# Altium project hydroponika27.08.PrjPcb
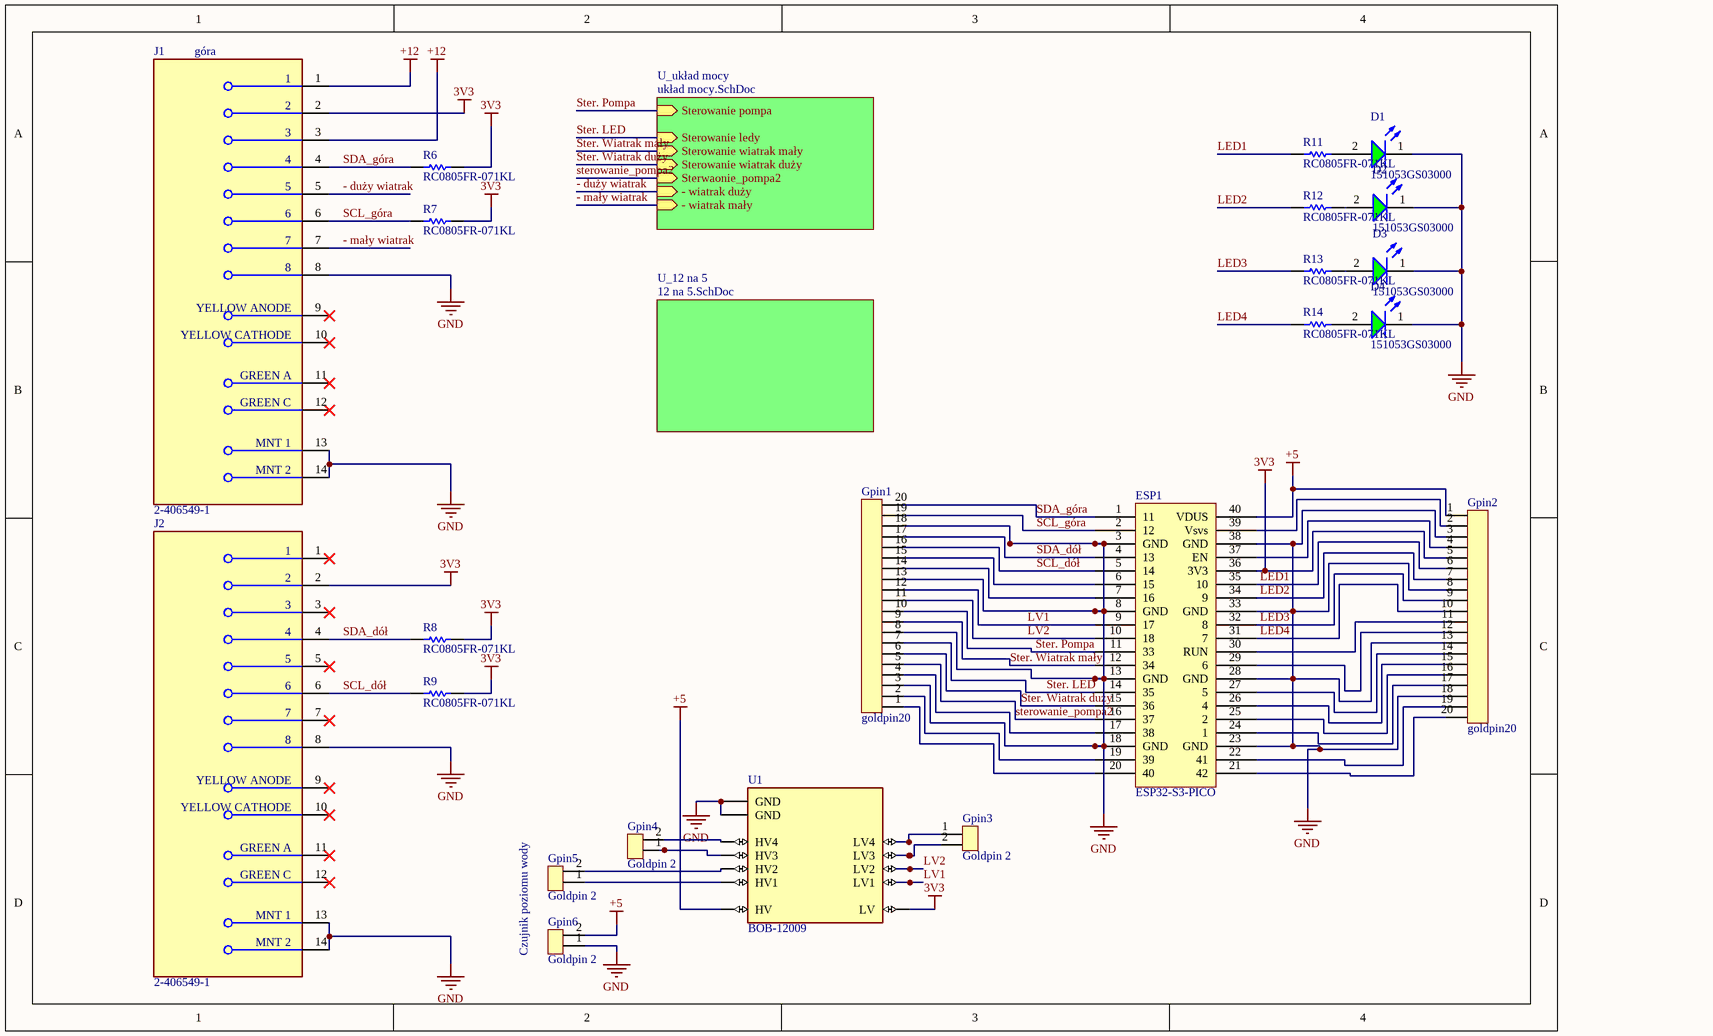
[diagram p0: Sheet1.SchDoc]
2 sheets, 30 parts. Net scope: hierarchical (ports join the sheet entries above them; power ports are global).
Board file: PCB1.PcbDoc
Sheets:
  Sheet1.SchDoc
    U_12 na 5 = 12 na 5.SchDoc

## Sheet Sheet1.SchDoc
size A4; SheetNumber: 1; SheetTotal: 3

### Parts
D1  151053GS03000  [WL-TMRW_D5.8H11.7]
D2  151053GS03000  [WL-TMRW_D5.8H11.7]
D3  151053GS03000  [WL-TMRW_D5.8H11.7]
D4  151053GS03000  [WL-TMRW_D5.8H11.7]
ESP1  ESP32-S3-PICO  [DIP40_ESP32]
Gpin1  goldpin20  [PCBComponent_1]
Gpin2  goldpin20  [PCBComponent_1]
Gpin3  Goldpin 2  [Goldpin 2]
Gpin4  Goldpin 2  [Goldpin 2]
Gpin5  Goldpin 2  [Goldpin 2]
Gpin6  Goldpin 2  [Goldpin 2]
J1  2-406549-1  [FP-2-406549-1-MFG]
J2  2-406549-1  [FP-2-406549-1-MFG]
R6  RC0805FR-071KL  [RESC2013X60X35ML10T20]
R7  RC0805FR-071KL  [RESC2013X60X35ML10T20]
R8  RC0805FR-071KL  [RESC2013X60X35ML10T20]
R9  RC0805FR-071KL  [RESC2013X60X35ML10T20]
R11  RC0805FR-071KL  [RESC2013X60X35ML10T20]
R12  RC0805FR-071KL  [RESC2013X60X35ML10T20]
R13  RC0805FR-071KL  [RESC2013X60X35ML10T20]
R14  RC0805FR-071KL  [RESC2013X60X35ML10T20]
U1  BOB-12009  [CONV_BOB-12009]

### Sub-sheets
U_12 na 5 = 12 na 5.SchDoc: no entries
U_układ mocy = układ mocy.SchDoc (file not in this document): Sterowanie pompa (in), Sterowanie ledy (in), Sterowanie wiatrak mały (in), Sterowanie wiatrak duży (in), - wiatrak duży (in), - wiatrak mały (in), Sterwaonie_pompa2 (in)

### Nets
3V3: ESP1.36(3V3) Gpin2.5 J1.2 J2.2 R6.2 R7.2 R8.2 R9.2 U1.LV
+5: ESP1.40(VDUS) Gpin2.1 Gpin6.2 U1.HV  [project net +vout_5]
+12: J1.1 J1.3  [project net +vin_12]
GND: D1.1(K) D2.1(K) D3.1(K) D4.1(K) ESP1.3(GND) ESP1.8(GND) ESP1.13(GND) ESP1.18(GND) ESP1.23(GND) ESP1.28(GND) ESP1.33(GND) ESP1.38(GND) Gpin1.3 Gpin1.8 Gpin1.13 Gpin1.18 Gpin2.3 Gpin2.8 Gpin2.13 Gpin2.18 Gpin6.1 J1.8 J1.13(MNT_1) J1.14(MNT_2) J2.8 J2.13(MNT_1) J2.14(MNT_2) U1.GND_1(GND) U1.GND_2(GND)  [project net - vout_5]
- duży wiatrak: J1.5 ; sheet U_układ mocy/- wiatrak duży
- mały wiatrak: J1.7 ; sheet U_układ mocy/- wiatrak mały
LED1: ESP1.35(10) Gpin2.6 R11.1
LED2: ESP1.34(9) Gpin2.7 R12.1
LED3: ESP1.32(8) Gpin2.9 R13.1
LED4: ESP1.31(7) Gpin2.10 R14.1
LV1: ESP1.9(17) Gpin1.12 U1.LV1
LV2: ESP1.10(18) Gpin1.11 U1.LV2
SCL_dół: ESP1.5(14) Gpin1.16 J2.6 R9.1
SCL_góra: ESP1.2(12) Gpin1.19 J1.6 R7.1
SDA_dół: ESP1.4(13) Gpin1.17 J2.4 R8.1
SDA_góra: ESP1.1(11) Gpin1.20 J1.4 R6.1
Ster. LED: ESP1.14(35) Gpin1.7 ; sheet U_układ mocy/Sterowanie ledy
Ster. Pompa: ESP1.11(33) Gpin1.10 ; sheet U_układ mocy/Sterowanie pompa
Ster. Wiatrak duży: ESP1.15(36) Gpin1.6 ; sheet U_układ mocy/Sterowanie wiatrak duży
Ster. Wiatrak mały: ESP1.12(34) Gpin1.9 ; sheet U_układ mocy/Sterowanie wiatrak mały
sterowanie_pompa2: ESP1.16(37) Gpin1.5 ; sheet U_układ mocy/Sterwaonie_pompa2
NetD1_2: D1.2(A) R11.2
NetD2_2: D2.2(A) R12.2
NetD3_2: D3.2(A) R13.2
NetD4_2: D4.2(A) R14.2
NetESP1_6: ESP1.6(15) Gpin1.15
NetESP1_7: ESP1.7(16) Gpin1.14
NetESP1_17: ESP1.17(38) Gpin1.4
NetESP1_19: ESP1.19(39) Gpin1.2
NetESP1_20: ESP1.20(40) Gpin1.1
NetESP1_21: ESP1.21(42) Gpin2.20
NetESP1_22: ESP1.22(41) Gpin2.19
NetESP1_24: ESP1.24(1) Gpin2.17
NetESP1_25: ESP1.25(2) Gpin2.16
NetESP1_26: ESP1.26(4) Gpin2.15
NetESP1_27: ESP1.27(5) Gpin2.14
NetESP1_29: ESP1.29(6) Gpin2.12
NetESP1_30: ESP1.30(RUN) Gpin2.11
NetESP1_37: ESP1.37(EN) Gpin2.4
NetESP1_39: ESP1.39(Vsvs) Gpin2.2
NetGpin3_1: Gpin3.1 U1.LV4
NetGpin3_2: Gpin3.2 U1.LV3
NetGpin4_1: Gpin4.1 U1.HV3
NetGpin4_2: Gpin4.2 U1.HV4
NetGpin5_1: Gpin5.1 U1.HV1
NetGpin5_2: Gpin5.2 U1.HV2

Not connected (* = marked no-connect by the designer): J1 9(YELLOW_ANODE)* 10(YELLOW_CATHODE)* 11(GREEN_A)* 12(GREEN_C)*; J2 1* 3* 5* 7* 9(YELLOW_ANODE)* 10(YELLOW_CATHODE)* 11(GREEN_A)* 12(GREEN_C)*

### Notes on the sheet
- góra
- Czujnik poziomu wody

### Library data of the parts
D1-D4 = CMP-1489-00005-2: NexarPartId: 29717817; Viewing Angle: 30°; Color: Green; Wavelength: 522nm; Max Reverse Voltage (DC): 5V; Test Current: 20mA; Forward Current: 100mA; Forward Voltage: 3.4V; Lens Style: Circular, Clear, Round; Luminous Intensity: 10cd; Lens Size: 5mm; Peak Wavelength: 515nm
J1 J2 = CMP-2000-05541-2: CONN MOD JACK 8P8C R/A SHIELDED; Max Voltage Rating (AC): 150V; Number of Contacts: 8; PCB Mounting Orientation: Right Angle; Direction: Up; Pitch: 2.03mm; Number of Ports: 1; Gender: Female; Tail Length: 2.54mm; Current Rating: 1.5A; Keyed: No; Approvals: UL; PCB Thickness: 1.57mm; Element Configuration: Single
R6-R9 R11-R14 = CMP-2100-03671-1: Chip Resistor, 1 KOhm, +/- 1%, 125 mW, -55 to 155 degC, 0805 (2012 Metric), RoHS, Tape and Reel; Manufacturer: Yageo; Temperature Coefficient: 100ppm/degreesC; Voltage Rating (DC): 150V; Max Power Dissipation: 125mW; Resistance: 1KOhm
U1 = BOB-12009: BSS138 - Logic-Level Translator Interface Evaluation Board; MF: SparkFun

## Sheet 12 na 5.SchDoc
size A4; SheetNumber: 3; SheetTotal: 3
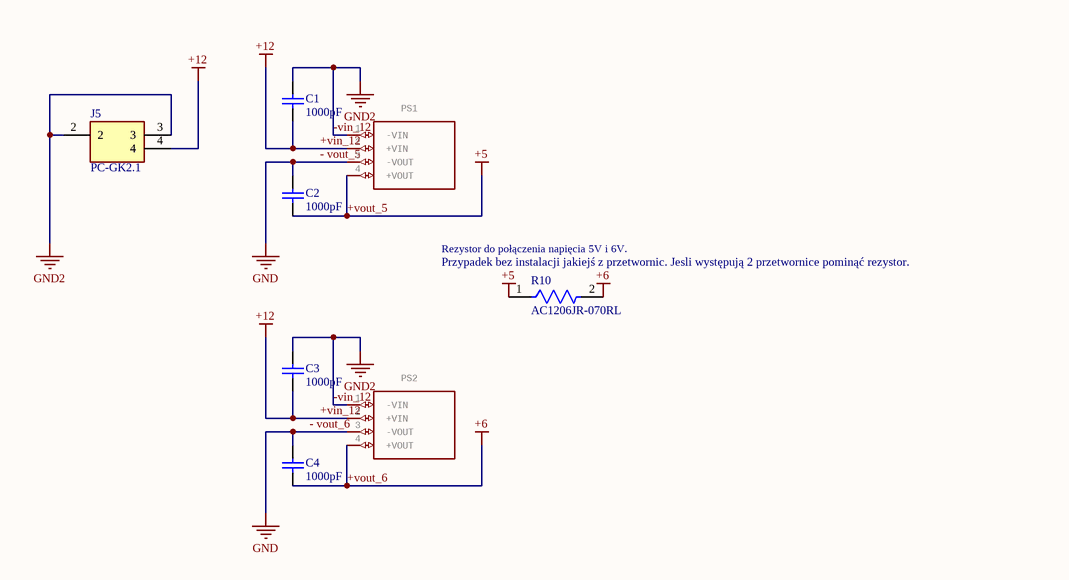
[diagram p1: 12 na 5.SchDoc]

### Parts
C1  1000pF  [CAPC4620X180X75LL50T35]
C2  1000pF  [CAPC4620X180X75LL50T35]
C3  1000pF  [CAPC4620X180X75LL50T35]
C4  1000pF  [CAPC4620X180X75LL50T35]
J5  PC-GK2.1  [PCGK21]
PS1  Isolated DC/DC Converters - Through Hole DC-DC CONVERTER, ISOLATED MODULE, SINGLE OUTPUT, 9.6V-14.4VDC INPUT, 5VDC OUTPUT, 1W   Source:  Datasheet  [EC3T12S05P]  (value not drawn)
PS2  Isolated DC/DC Converters - Through Hole DC-DC CONVERTER, ISOLATED MODULE, SINGLE OUTPUT, 9.6V-14.4VDC INPUT, 5VDC OUTPUT, 1W   Source:  Datasheet  [EC3T12S05P]  (value not drawn)
R10  AC1206JR-070RL  [FP-AC1206-0_65-MFG]

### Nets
+vin_12: C1.1 C3.1 J5.4 PS1.2(+VIN) PS2.2(+VIN)  [also labelled +12]
+vout_5: C2.1 PS1.4(+VOUT) R10.1  [also labelled +5]
+vout_6: C4.1 PS2.4(+VOUT) R10.2  [also labelled +6]
- vout_5: C2.2 C4.2 PS1.3(-VOUT) PS2.3(-VOUT)  [also labelled - vout_6, GND]
-vin_12: C1.2 C3.2 J5.2 J5.3 PS1.1(-VIN) PS2.1(-VIN)  [also labelled GND2]

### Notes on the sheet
- (near R10) Rezystor do połączenia napięcia 5V i 6V.
- (near R10) Przypadek bez instalacji jakiejś z przetwornic. Jesli występują 2 przetwornice pominąć rezystor.

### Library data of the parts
C1-C4 = CMP-2000-05503-1: Chip Capacitor, 1000 pF, +/- 10%, 2000 V, -55 to 125 degC, 1808 (4520 Metric), RoHS, Tape and Reel; Manufacturer: AVX; Rated Voltage: 2000V; Dielectric: X7R; Capacitance: 1nF
J5 = PC-GK2.1: Connector; Manufacturer_Name: Ninigi
PS1 PS2 = EC3T-12S05P: Manufacturer_Name: Adam Tech; GateName_1: G$1
R10 = CMP-2003-04900-2: RES SMD 0 OHM JUMPER 1/4W 1206; Tolerance: 5%; Temperature Coefficient: 200ppm/°C; Power Rating: 250mW; Resistance: 0R; Voltage Rating: 200V

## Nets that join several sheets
+vin_12: Sheet1 (J1.1 J1.3), 12 na 5 (5 pins)
+vout_5: Sheet1 (ESP1.40 Gpin2.1 Gpin6.2 U1.HV), 12 na 5 (C2.1 PS1.4 R10.1)
- vout_5: Sheet1 (29 pins), 12 na 5 (C2.2 C4.2 PS1.3 PS2.3)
